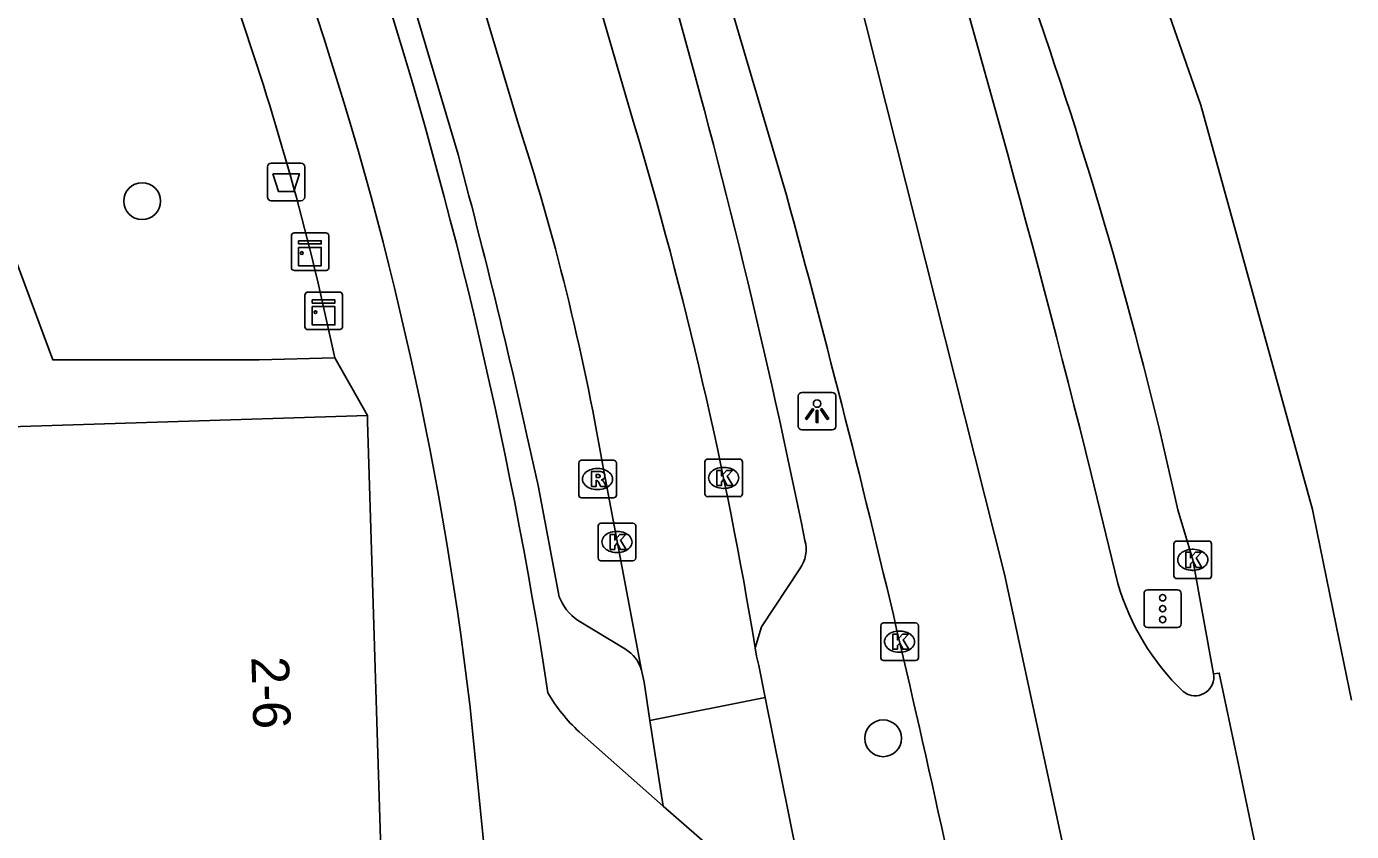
# Model space of a CAD drawing. Extents: x 161402 to 161933, y 381650 to 382313.
# Drawn here: x 161897.66 to 161932.93, y 382147.3 to 382168.72 of the extents above; entities that cross this region are included whole.
import ezdxf

# ---------------------------------------------------------------- set-up
doc = ezdxf.new("R2010")
doc.units = 0
for name, color, linetype in [('IMGEO_Afvalbak', 7, 'Continuous'), ('IMGEO_Boom', 7, 'Continuous'), ('IMGEO_Fietspad_gesloten', 7, 'Continuous'), ('IMGEO_Kast', 7, 'Continuous'), ('IMGEO_Kolk', 7, 'Continuous'), ('IMGEO_Lichtpunt', 7, 'Continuous'), ('IMGEO_OVBaan_gesloten', 7, 'Continuous'), ('IMGEO_Pand', 7, 'Continuous'), ('IMGEO_Pand_nummerreeks', 7, 'Continuous'), ('IMGEO_Parkeervlak_open', 7, 'Continuous'), ('IMGEO_Rijbaan_lokaal_gesloten', 7, 'Continuous'), ('IMGEO_Rijbaan_lokaal_open', 7, 'Continuous'), ('IMGEO_Rioolput', 7, 'Continuous'), ('IMGEO_Verkeersregelinstallatiepaal', 7, 'Continuous'), ('IMGEO_Voetpad_open', 7, 'Continuous')]:
    doc.layers.add(name, color=color, linetype=linetype)

msp = doc.modelspace()

# ---------------------------------------------------------------- linework, layer by layer
at = {"layer": 'IMGEO_Afvalbak'}
for p, q in [((161904.174, 382165.082), (161904.964, 382165.082)), ((161904.964, 382165.082), (161904.174, 382165.082)), ((161904.074, 382164.182), (161904.074, 382164.982)), ((161904.074, 382164.982), (161904.074, 382164.182)), ((161905.064, 382164.982), (161905.064, 382164.182)), ((161905.064, 382164.182), (161905.064, 382164.982)), ((161904.964, 382164.082), (161904.174, 382164.082)), ((161904.174, 382164.082), (161904.964, 382164.082))]:
    msp.add_line(p, q, dxfattribs=at)
msp.add_lwpolyline([(161904.217, 382164.796), (161904.921, 382164.796), (161904.772, 382164.326), (161904.366, 382164.326), (161904.217, 382164.796)], dxfattribs=at)
for centre, start, end in [((161904.174, 382164.982), 90, 180), ((161904.174, 382164.982), 90, 180), ((161904.964, 382164.982), 0, 90), ((161904.964, 382164.982), 360, 90), ((161904.174, 382164.182), 180, 270), ((161904.174, 382164.182), 180, 270), ((161904.964, 382164.182), 270, 0), ((161904.964, 382164.182), 270, 0)]:
    msp.add_arc(centre, 0.1, start, end, dxfattribs=at)
at = {"layer": 'IMGEO_Boom'}
for centre in [(161900.734, 382164.072), (161920.463, 382149.777)]:
    msp.add_circle(centre, 0.489, dxfattribs=at)
at = {"layer": 'IMGEO_Fietspad_gesloten'}
for points in [[(161910.052, 382144.744), (161909.457, 382150.678)], [(161912.371, 382149.949), (161914.606, 382147.976)]]:
    msp.add_lwpolyline(points, dxfattribs=at)
for centre, radius, start, end in [((161786.886, 382131.793), 126.122, 8.75367, 18.09567), ((161816.056, 382139.513), 94.066, 6.81682, 19.0208), ((161915.305, 382153.153), 4.344, 209.9059, 227.5213)]:
    msp.add_arc(centre, radius, start, end, dxfattribs=at)
at = {"layer": 'IMGEO_Kast'}
for p, q in [((161904.707, 382162.302), (161904.707, 382163.143)), ((161904.707, 382163.143), (161904.707, 382162.302)), ((161904.782, 382163.227), (161905.623, 382163.227)), ((161905.623, 382163.227), (161904.782, 382163.227)), ((161905.707, 382163.152), (161905.707, 382162.311)), ((161905.707, 382162.311), (161905.707, 382163.152)), ((161905.632, 382162.227), (161904.791, 382162.227)), ((161904.791, 382162.227), (161905.632, 382162.227)), ((161905.07, 382160.728), (161905.07, 382161.569)), ((161905.07, 382161.569), (161905.07, 382160.728)), ((161905.145, 382161.653), (161905.986, 382161.653)), ((161905.986, 382161.653), (161905.145, 382161.653)), ((161906.07, 382161.578), (161906.07, 382160.737)), ((161906.07, 382160.737), (161906.07, 382161.578)), ((161905.995, 382160.653), (161905.154, 382160.653)), ((161905.154, 382160.653), (161905.995, 382160.653))]:
    msp.add_line(p, q, dxfattribs=at)
for points in [[(161904.902, 382163.017), (161905.502, 382163.017), (161905.502, 382162.932), (161904.902, 382162.932), (161904.902, 382163.017)], [(161904.902, 382162.842), (161905.502, 382162.842), (161905.502, 382162.353), (161904.902, 382162.353), (161904.902, 382162.842)], [(161905.265, 382161.443), (161905.865, 382161.443), (161905.865, 382161.358), (161905.265, 382161.358), (161905.265, 382161.443)], [(161905.265, 382161.268), (161905.865, 382161.268), (161905.865, 382160.779), (161905.265, 382160.779), (161905.265, 382161.268)]]:
    msp.add_lwpolyline(points, dxfattribs=at)
for centre in [(161904.986, 382162.691), (161905.349, 382161.117)]:
    msp.add_circle(centre, 0.0377, dxfattribs=at)
for centre, start, end in [((161904.785, 382163.149), 92.4484, 184.2845), ((161904.785, 382163.149), 92.4484, 184.2845), ((161905.629, 382163.149), 2.4484, 94.2845), ((161905.629, 382163.149), 2.4484, 94.2845), ((161904.785, 382162.305), 182.4484, 274.2845), ((161904.785, 382162.305), 182.4484, 274.2845), ((161905.629, 382162.305), 272.4484, 4.2845), ((161905.629, 382162.305), 272.4484, 4.2845), ((161905.148, 382161.575), 92.4484, 184.2845), ((161905.148, 382161.575), 92.4484, 184.2845), ((161905.992, 382161.575), 2.4484, 94.2845), ((161905.992, 382161.575), 2.4484, 94.2845), ((161905.148, 382160.731), 182.4484, 274.2845), ((161905.148, 382160.731), 182.4484, 274.2845), ((161905.992, 382160.731), 272.4484, 4.2845), ((161905.992, 382160.731), 272.4484, 4.2845)]:
    msp.add_arc(centre, 0.0779, start, end, dxfattribs=at)
at = {"layer": 'IMGEO_Kolk'}
for p, q in [((161915.717, 382156.282), (161915.717, 382157.134)), ((161915.792, 382157.208), (161916.644, 382157.208)), ((161916.205, 382156.988), (161916.23, 382156.988)), ((161916.718, 382157.134), (161916.718, 382156.282)), ((161916.644, 382156.208), (161915.792, 382156.208)), ((161916.228, 382156.428), (161916.203, 382156.428)), ((161912.95, 382155.502), (161913.802, 382155.502)), ((161912.875, 382154.576), (161912.875, 382155.428)), ((161913.363, 382155.282), (161913.388, 382155.282)), ((161913.876, 382155.428), (161913.876, 382154.576)), ((161928.205, 382154.101), (161928.205, 382154.953)), ((161928.28, 382155.027), (161929.132, 382155.027)), ((161928.693, 382154.807), (161928.718, 382154.807)), ((161929.206, 382154.953), (161929.206, 382154.101)), ((161913.802, 382154.502), (161912.95, 382154.502)), ((161913.386, 382154.722), (161913.361, 382154.722)), ((161928.716, 382154.247), (161928.691, 382154.247)), ((161929.132, 382154.027), (161928.28, 382154.027)), ((161920.4, 382151.922), (161920.4, 382152.774)), ((161920.475, 382152.848), (161921.327, 382152.848)), ((161921.401, 382152.774), (161921.401, 382151.922)), ((161920.888, 382152.628), (161920.913, 382152.628)), ((161920.911, 382152.068), (161920.886, 382152.068)), ((161921.327, 382151.848), (161920.475, 382151.848))]:
    msp.add_line(p, q, dxfattribs=at)
for points in [[(161915.717, 382156.282), (161915.717, 382157.134)], [(161915.792, 382157.208), (161916.644, 382157.208)], [(161916.038, 382156.908), (161916.161, 382156.908), (161916.161, 382156.757), (161916.291, 382156.908), (161916.455, 382156.908), (161916.309, 382156.757), (161916.462, 382156.508), (161916.31, 382156.508), (161916.225, 382156.672), (161916.161, 382156.605), (161916.161, 382156.508), (161916.038, 382156.508), (161916.038, 382156.908)], [(161916.718, 382157.134), (161916.718, 382156.282)], [(161916.644, 382156.208), (161915.792, 382156.208)], [(161912.95, 382155.502), (161913.802, 382155.502)], [(161912.875, 382154.576), (161912.875, 382155.428)], [(161913.196, 382155.202), (161913.319, 382155.202), (161913.319, 382155.051), (161913.449, 382155.202), (161913.613, 382155.202), (161913.467, 382155.051), (161913.62, 382154.802), (161913.468, 382154.802), (161913.383, 382154.966), (161913.319, 382154.899), (161913.319, 382154.802), (161913.196, 382154.802), (161913.196, 382155.202)], [(161913.876, 382155.428), (161913.876, 382154.576)], [(161928.205, 382154.101), (161928.205, 382154.953)], [(161928.28, 382155.027), (161929.132, 382155.027)], [(161929.206, 382154.953), (161929.206, 382154.101)], [(161913.802, 382154.502), (161912.95, 382154.502)], [(161928.526, 382154.727), (161928.649, 382154.727), (161928.649, 382154.576), (161928.779, 382154.727), (161928.943, 382154.727), (161928.797, 382154.576), (161928.95, 382154.327), (161928.798, 382154.327), (161928.713, 382154.491), (161928.649, 382154.424), (161928.649, 382154.327), (161928.526, 382154.327), (161928.526, 382154.727)], [(161929.132, 382154.027), (161928.28, 382154.027)], [(161920.4, 382151.922), (161920.4, 382152.774)], [(161920.475, 382152.848), (161921.327, 382152.848)], [(161921.401, 382152.774), (161921.401, 382151.922)], [(161920.721, 382152.548), (161920.844, 382152.548), (161920.844, 382152.397), (161920.974, 382152.548), (161921.138, 382152.548), (161920.992, 382152.397), (161921.145, 382152.148), (161920.993, 382152.148), (161920.908, 382152.312), (161920.844, 382152.245), (161920.844, 382152.148), (161920.721, 382152.148), (161920.721, 382152.548)], [(161921.327, 382151.848), (161920.475, 382151.848)]]:
    msp.add_lwpolyline(points, dxfattribs=at)
for centre, start, end in [((161915.794, 382157.132), 91.552, 178.448), ((161915.794, 382157.132), 91.552, 178.448), ((161916.642, 382157.132), 1.552, 88.448), ((161916.642, 382157.132), 1.552, 88.448), ((161915.794, 382156.284), 181.552, 268.448), ((161915.794, 382156.284), 181.552, 268.448), ((161916.642, 382156.284), 271.552, 358.448), ((161916.642, 382156.284), 271.552, 358.448), ((161912.952, 382155.426), 91.552, 178.448), ((161912.952, 382155.426), 91.552, 178.448), ((161913.8, 382155.426), 1.552, 88.448), ((161913.8, 382155.426), 1.552, 88.448), ((161928.282, 382154.951), 91.552, 178.448), ((161928.282, 382154.951), 91.552, 178.448), ((161929.13, 382154.951), 1.552, 88.448), ((161929.13, 382154.951), 1.552, 88.448), ((161912.952, 382154.578), 181.552, 268.448), ((161912.952, 382154.578), 181.552, 268.448), ((161913.8, 382154.578), 271.552, 358.448), ((161913.8, 382154.578), 271.552, 358.448), ((161928.282, 382154.103), 181.552, 268.448), ((161928.282, 382154.103), 181.552, 268.448), ((161929.13, 382154.103), 271.552, 358.448), ((161929.13, 382154.103), 271.552, 358.448), ((161920.477, 382152.772), 91.552, 178.448), ((161920.477, 382152.772), 91.552, 178.448), ((161921.325, 382152.772), 1.552, 88.448), ((161921.325, 382152.772), 1.552, 88.448), ((161920.477, 382151.924), 181.552, 268.448), ((161920.477, 382151.924), 181.552, 268.448), ((161921.325, 382151.924), 271.552, 358.448), ((161921.325, 382151.924), 271.552, 358.448)]:
    msp.add_arc(centre, 0.0765, start, end, dxfattribs=at)
for centre, major_axis, ratio, start_param, end_param in [((161916.204, 382156.708), (-0.387, 0.002), 0.722429, 4.712389, 7.853982), ((161916.229, 382156.708), (-0.39, 0.002), 0.717154, 1.570796, 4.712389), ((161913.362, 382155.002), (-0.387, 0.002), 0.722429, 4.712389, 7.853982), ((161913.387, 382155.002), (-0.39, 0.002), 0.717154, 1.570796, 4.712389), ((161928.692, 382154.527), (-0.387, 0.002), 0.722429, 4.712389, 7.853982), ((161928.717, 382154.527), (-0.39, 0.002), 0.717154, 1.570796, 4.712389), ((161920.887, 382152.348), (-0.387, 0.002), 0.722429, 4.712389, 7.853982), ((161920.912, 382152.348), (-0.39, 0.002), 0.717154, 1.570796, 4.712389)]:
    msp.add_ellipse(centre, major_axis=major_axis, ratio=ratio, start_param=start_param, end_param=end_param, dxfattribs=at)
at = {"layer": 'IMGEO_Lichtpunt'}
for p, q in [((161918.205, 382158.887), (161918.205, 382158.08)), ((161918.205, 382158.887), (161918.205, 382158.08)), ((161919.107, 382158.982), (161918.299, 382158.982)), ((161919.107, 382158.982), (161918.299, 382158.982)), ((161919.201, 382158.08), (161919.201, 382158.887)), ((161919.201, 382158.08), (161919.201, 382158.887)), ((161918.299, 382157.986), (161919.107, 382157.986)), ((161918.299, 382157.986), (161919.107, 382157.986))]:
    msp.add_line(p, q, dxfattribs=at)
for points in [[(161918.579, 382158.551), (161918.618, 382158.523), (161918.43, 382158.261), (161918.392, 382158.288), (161918.579, 382158.551)], [(161918.681, 382158.503), (161918.728, 382158.503), (161918.728, 382158.181), (161918.681, 382158.181), (161918.681, 382158.503)], [(161918.791, 382158.523), (161918.829, 382158.55), (161919.016, 382158.288), (161918.977, 382158.26), (161918.791, 382158.523)]]:
    msp.add_lwpolyline(points, dxfattribs=at)
msp.add_circle((161918.704, 382158.685), 0.0994, dxfattribs=at)
for centre, start, end in [((161918.299, 382158.887), 90, 180), ((161918.299, 382158.887), 90, 180), ((161919.107, 382158.887), 0, 90), ((161919.107, 382158.887), 0, 90), ((161918.299, 382158.08), 180, 270), ((161918.299, 382158.08), 180, 270), ((161919.107, 382158.08), 270, 0), ((161919.107, 382158.08), 270, 360)]:
    msp.add_arc(centre, 0.0946, start, end, dxfattribs=at)
at = {"layer": 'IMGEO_OVBaan_gesloten'}
for points in [[(161883.94, 382296.053), (161887.492, 382285.515), (161891.555, 382273.464), (161899.181, 382251.493), (161905.587, 382233.642), (161913.746, 382209.878), (161922.363, 382185.389), (161928.921, 382166.622), (161929.639, 382164.026), (161931.896, 382155.865), (161931.923, 382155.731), (161932.527, 382152.775), (161932.932, 382150.79)], [(161928.311, 382155.861), (161928.706, 382154.527), (161929.259, 382151.489)], [(161929.259, 382151.489), (161929.41, 382151.511), (161929.894, 382149.203), (161931.045, 382143.716)]]:
    msp.add_lwpolyline(points, dxfattribs=at)
msp.add_arc((161813.636, 382130.461), 117.454, 12.48926, 19.32738, dxfattribs=at)
at = {"layer": 'IMGEO_Pand'}
for points in [[(161895.524, 382158.015), (161906.731, 382158.368)], [(161906.731, 382158.368), (161906.736, 382158.205), (161907.16, 382144.524), (161907.227, 382142.376)]]:
    msp.add_lwpolyline(points, dxfattribs=at)
at = {"layer": 'IMGEO_Parkeervlak_open'}
for points in [[(161909.147, 382165.309), (161903.986, 382182.668)], [(161911.84, 382153.545), (161911.274, 382156.501)], [(161918.244, 382154.29), (161917.222, 382152.743), (161917.058, 382152.186)], [(161913.604, 382152.15), (161912.33, 382152.919)]]:
    msp.add_lwpolyline(points, dxfattribs=at)
for centre, radius, start, end in [((161724.367, 382115.726), 197.956, 11.45481, 15.8104), ((161732.18, 382117.913), 183.204, 12.1591, 14.99321), ((161917.53, 382154.807), 0.882, 324.1298, 15.2875), ((161913.077, 382154.008), 1.321, 200.5403, 235.5636), ((161913.091, 382151.32), 0.975, 15.9962, 58.2972)]:
    msp.add_arc(centre, radius, start, end, dxfattribs=at)
at = {"layer": 'IMGEO_Rijbaan_lokaal_gesloten'}
for points in [[(161926.032, 382143.324), (161923.698, 382154.142), (161918.698, 382173.962), (161914.783, 382185.665), (161890.773, 382250.034), (161885.821, 382262.869), (161874.965, 382293.393)], [(161909.37, 382191.051), (161909.49, 382190.867), (161909.812, 382189.677), (161915.006, 382174.034), (161915.06, 382173.83), (161917.891, 382164.229)], [(161926.711, 382153.894), (161926.004, 382156.819)], [(161928.544, 382150.962), (161928.449, 382151.022)]]:
    msp.add_lwpolyline(points, dxfattribs=at)
for centre, radius, start, end in [((161556.754, 382064.669), 380.575, 14.01256, 17.03322), ((161592.988, 382075.551), 336.787, 11.08317, 15.26628), ((161933.002, 382155.739), 6.556, 196.3471, 226.0136), ((161928.769, 382151.405), 0.497, 243.0639, 9.7212)]:
    msp.add_arc(centre, radius, start, end, dxfattribs=at)
at = {"layer": 'IMGEO_Rijbaan_lokaal_open'}
for points in [[(161905.035, 382185.281), (161910.729, 382166.198)], [(161913.81, 382166.2), (161908.762, 382183.554)], [(161912.998, 382157.038), (161914.029, 382151.589)], [(161917.058, 382152.186), (161917.094, 382151.965), (161917.149, 382151.718), (161917.321, 382150.865)], [(161914.255, 382150.247), (161914.097, 382151.273), (161914.029, 382151.589)], [(161914.255, 382150.247), (161917.321, 382150.865)], [(161917.321, 382150.865), (161918.606, 382144.49)], [(161914.606, 382147.976), (161914.255, 382150.247)], [(161918.606, 382144.49), (161914.606, 382147.976)]]:
    msp.add_lwpolyline(points, dxfattribs=at)
for centre, radius, start, end in [((161848.933, 382146.03), 65.004, 9.74997, 18.07512), ((161805.494, 382133.713), 113.083, 9.40213, 16.69577)]:
    msp.add_arc(centre, radius, start, end, dxfattribs=at)
at = {"layer": 'IMGEO_Rioolput'}
for p, q in [((161912.359, 382156.25), (161912.359, 382157.102)), ((161912.434, 382157.176), (161913.286, 382157.176)), ((161912.847, 382156.956), (161912.872, 382156.956)), ((161913.36, 382157.102), (161913.36, 382156.25)), ((161913.286, 382156.176), (161912.434, 382156.176)), ((161912.87, 382156.396), (161912.845, 382156.396))]:
    msp.add_line(p, q, dxfattribs=at)
for points in [[(161912.359, 382156.25), (161912.359, 382157.102)], [(161912.434, 382157.176), (161913.286, 382157.176)], [(161913.36, 382157.102), (161913.36, 382156.25)], [(161912.948, 382156.874), (161912.696, 382156.876), (161912.696, 382156.476)], [(161912.696, 382156.476), (161912.82, 382156.476), (161912.82, 382156.638), (161912.831, 382156.638)], [(161912.874, 382156.795), (161912.82, 382156.795), (161912.82, 382156.714)], [(161912.82, 382156.714), (161912.872, 382156.714)], [(161912.878, 382156.609), (161912.949, 382156.476), (161913.089, 382156.476), (161913.024, 382156.602)], [(161913.286, 382156.176), (161912.434, 382156.176)]]:
    msp.add_lwpolyline(points, dxfattribs=at)
for centre, radius, start, end in [((161912.436, 382157.1), 0.0765, 91.552, 178.448), ((161912.436, 382157.1), 0.0765, 91.552, 178.448), ((161913.284, 382157.1), 0.0765, 1.552, 88.448), ((161913.284, 382157.1), 0.0765, 1.552, 88.448), ((161912.83, 382156.585), 0.0533, 26.0293, 88.6989), ((161912.856, 382156.903), 0.19, 274.7715, 282.9687), ((161912.88, 382156.699), 0.0964, 77.0061, 93.1865), ((161912.894, 382156.756), 0.0378, 276.6634, 79.6772), ((161912.947, 382156.764), 0.109, 350.3612, 89.416), ((161912.945, 382156.764), 0.112, 277.5842, 350.9817), ((161912.929, 382156.549), 0.108, 29.5134, 73.7905), ((161912.436, 382156.252), 0.0765, 181.552, 268.448), ((161912.436, 382156.252), 0.0765, 181.552, 268.448), ((161913.284, 382156.252), 0.0765, 271.552, 358.448), ((161913.284, 382156.252), 0.0765, 271.552, 358.448)]:
    msp.add_arc(centre, radius, start, end, dxfattribs=at)
for centre, major_axis, ratio, start_param, end_param in [((161912.846, 382156.676), (-0.387, 0.002), 0.722429, 4.712389, 7.853982), ((161912.871, 382156.676), (-0.39, 0.002), 0.717154, 1.570796, 4.712389)]:
    msp.add_ellipse(centre, major_axis=major_axis, ratio=ratio, start_param=start_param, end_param=end_param, dxfattribs=at)
at = {"layer": 'IMGEO_Verkeersregelinstallatiepaal'}
for p, q in [((161927.509, 382153.727), (161928.299, 382153.727)), ((161928.299, 382153.727), (161927.509, 382153.727)), ((161927.409, 382152.827), (161927.409, 382153.627)), ((161927.409, 382153.627), (161927.409, 382152.827)), ((161928.399, 382153.627), (161928.399, 382152.827)), ((161928.399, 382152.827), (161928.399, 382153.627)), ((161928.299, 382152.727), (161927.509, 382152.727)), ((161927.509, 382152.727), (161928.299, 382152.727))]:
    msp.add_line(p, q, dxfattribs=at)
for centre in [(161927.904, 382153.517), (161927.904, 382153.227), (161927.904, 382152.937)]:
    msp.add_circle(centre, 0.085, dxfattribs=at)
for centre, start, end in [((161927.509, 382153.627), 90, 180), ((161927.509, 382153.627), 90, 180), ((161928.299, 382153.627), 0, 90), ((161928.299, 382153.627), 360, 90), ((161927.509, 382152.827), 180, 270), ((161927.509, 382152.827), 180, 270), ((161928.299, 382152.827), 270, 0), ((161928.299, 382152.827), 270, 0)]:
    msp.add_arc(centre, 0.1, start, end, dxfattribs=at)
at = {"layer": 'IMGEO_Voetpad_open'}
for points in [[(161905.864, 382159.898), (161903.846, 382159.846), (161898.358, 382159.847), (161895.511, 382167.486), (161893.053, 382167.011), (161891.789, 382168.338)], [(161905.401, 382161.971), (161905.864, 382159.898)], [(161906.731, 382158.368), (161905.864, 382159.898)]]:
    msp.add_lwpolyline(points, dxfattribs=at)
msp.add_arc((161832.145, 382144.455), 75.321, 13.4469, 20.34289, dxfattribs=at)

# ---------------------------------------------------------------- texts
at = {"layer": 'IMGEO_Pand_nummerreeks'}
msp.add_text('2-6', height=1, rotation=271.6563, dxfattribs=at).set_placement((161903.642, 382151.944))

doc.saveas('drawing.dxf')
